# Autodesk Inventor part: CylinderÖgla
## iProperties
Created: 2007-04
Part Number: CylinderÖgla
Document SubType Name: Modeling
Designer: kurs1
Density: 1 g/cm^3
Author: kurs1
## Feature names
1. Extrusion1
2. Hole2
3. Hole3
